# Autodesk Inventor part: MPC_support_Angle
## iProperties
Shininess: 64.0
Length Units: 11269
Angle Units: 11279
Time Units: 11290
Mass Units: 11283
Length Display Precision: 3
Angle Display Precision: 2
Compacted: True
Part Number: MPC_support_Angle
Document SubType Name: Modeling
Created: 2004-08
Material: Aluminum-6061
Designer: John Blackburn
Manufacturer: Standard
Standards Organization: Custom
Density: 0.0
Volumn: 0.0
Area: 0.0
PropertySet Name: Model Information
Control State: 0
Master: False
Checked Out: False
Author: John Blackburn
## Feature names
1. Extrusion1
2. Chamfer1
3. Hole1
4. Extrusion2
5. Extrusion3
